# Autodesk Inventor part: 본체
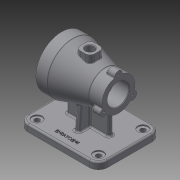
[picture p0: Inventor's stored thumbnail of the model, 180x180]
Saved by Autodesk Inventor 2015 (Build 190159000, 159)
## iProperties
Created: 2021-10
Part Number: 본체
Material: 일반
Document SubType Name: Modeling
Designer: 1019876
Density: 1 g/cm^3
Appearance: 기본값
Author: 1019876
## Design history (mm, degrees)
sketch "스케치1"
  geometry: L1 (70, 55)-(-70, 55); L2 (-70, 55)-(-70, -55); L3 (-70, -55)-(70, -55); L4 (70, -55)-(70, 55); L5 (70, 55)-(-70, -55); L6 (-70, 55)-(70, -55); 1 further point
  constraints: 12 end point, 2 midpoint, 2 parallel, 1 horizontal, 1 perpendicular
  dimensions: "d0" = 140 distance of L3.end L2.end; "d1" = 110 distance of L2.end L1.end
extrude "돌출1" new body sketch "스케치1" distance "d2" = 12; taper "d3" = 0 deg
sketch "스케치2"
  geometry: L1 (-54, -39)-(54, -39); L2 (54, -39)-(54, 39); L3 (54, 39)-(-54, 39); L4 (-54, 39)-(-54, -39); L5 (-54, -39)-(54, 39); L6 (54, -39)-(-54, 39); 5 further points
  constraints: 12 end point, 4 coincident, 2 midpoint, 2 parallel, 1 horizontal, 1 perpendicular
  dimensions: "d4" = 108 distance of L3.end L2.end; "d5" = 78 distance of L2.end L1.end
hole "구멍1" sketch "스케치2" at (-54, 39), (54, -39), (54, 39), (-54, -39) diameter "d6" = 9; stored, may be unused: countersink angle "d10" = 90 deg, drill point angle "d12" = 118 deg; dims "d7" = 6, "d8" = 18, "d9" = 2, "d11" = 28
sketch "스케치3"
  geometry: L1 (-50, 82)-(50, 82); L2 (-50, 82)-(-50, 127); L3 (-50, 127)-(-30, 127); L4 (-30, 127)-(27, 111); L5 (27, 111)-(50, 111); L6 (50, 111)-(50, 82); L7 (70, 0)-(-70, 0) reference; 2 further points
  constraints: 12 end point, 1 horizontal, 1 midpoint, 1 parallel, 1 perpendicular, 1 vertical, 1 vertical alignment
  dimensions: "d13" = 90 diameter of L3 L1; "d15" = 82 distance between parallel lines of L7 L1; "d16" = 20 distance of L2.end L3.end; "d18" = 23 distance from line of L6 L4.end; "d19" = 100 distance between parallel lines of L6 L2; "d21" = 58 diameter of L5 L1
revolve "회전1" sketch "스케치3" stored, may be unused: angle "d22" = 90 deg
sketch "스케치4"
  geometry: L1 (0, 29)-(0, 0); L2 (0, 0)-(-25.115, -14.5); L3 (0, 0)-(25.115, -14.5); C1 r 7 at (0, 29); C2 r 7 at (-25.115, -14.5); C3 r 7 at (25.115, -14.5); A1 r 29 centre (0, 0) between (0, 29) and (-25.115, -14.5) reference; 1 further point
  constraints: 6 end point, 3 centre point, 3 point on circle, 2 coincident, 1 vertical, 1 vertical alignment
  dimensions: "d23" = 14 diameter of C1; "d24" = 120 deg angle of L2 L1; "d25" = 120 deg angle of L2 L3; "d26" = 14 diameter of C2; "d27" = 14 diameter of C3
extrude "돌출2" join sketch "스케치4" distance "d28" = 15; taper "d29" = 0 deg
node "작업 평면1"
sketch "스케치5"
  geometry: L1 (12.5, 12.5)-(-12.5, 12.5); L2 (-12.5, 12.5)-(-12.5, -12.5); L3 (-12.5, -12.5)-(12.5, -12.5); L4 (12.5, -12.5)-(12.5, 12.5); L5 (12.5, 12.5)-(-12.5, -12.5); L6 (-12.5, 12.5)-(12.5, -12.5); 1 further point
  constraints: 12 end point, 2 midpoint, 2 parallel, 1 horizontal, 1 perpendicular
  dimensions: "d31" = 25 distance of L3.end L2.end; "d32" = 25 distance of L2.end L1.end
extrude "돌출3" join sketch "스케치5" distance "d33" = 23.5; taper "d34" = 0 deg
sketch "스케치6"
  geometry: 2 further points
  constraints: 1 coincident
hole "구멍2" sketch "스케치6" at (0, 0) diameter "d35" = 15; stored, may be unused: countersink angle "d39" = 90 deg, drill point angle "d41" = 118 deg; dims "d36" = 6, "d37" = 18, "d38" = 2, "d40" = 38.25
sketch "스케치7"
  geometry: L1 (-50, 37)-(-50, 127) reference; L2 (-50, 82)-(50, 82); L3 (50, 73.94)-(50, 110.155) reference; L4 (-50, 82)-(-50, 113); L5 (-50, 113)-(-30, 113); L6 (-27, 110)-(-27, 110); L7 (-24, 107)-(17, 107); L8 (20, 104)-(20, 104); L9 (23, 101)-(50, 101); L10 (50, 82)-(50, 101); A1 r 3 centre (-30, 110) between (-27, 110) and (-30, 113); A2 r 3 centre (-24, 110) between (-27, 110) and (-24, 107); A3 r 3 centre (17, 104) between (20, 104) and (17, 107); A4 r 3 centre (23, 104) between (20, 104) and (23, 101); 3 further points
  constraints: 16 end point, 8 point on circle, 8 tangent, 7 point on line, 5 perpendicular, 4 centre point, 3 equal radius, 2 horizontal, 1 midpoint
  dimensions: "d42" = 23 distance between parallel lines of L6 L1; "d43" = 47 distance of point (-27, 107) point (20, 107); "d44" = 62 diameter of L5 L2; "d45" = 50 diameter of L7 L2; "d46" = 38 diameter of L9 L2; "d47" = 3 radius of A1
revolve "회전2" sketch "스케치7" stored, may be unused: angle "d48" = 90 deg
sketch "스케치8"
  geometry: L1 (-37, -4)-(37, -4); L2 (37, -4)-(37, 4); L3 (37, 4)-(-37, 4); L4 (-37, 4)-(-37, -4); L5 (-37, -4)-(37, 4); L6 (37, -4)-(-37, 4); L7 (-4, -24)-(4, -24); L8 (4, -24)-(4, 24); L9 (4, 24)-(-4, 24); L10 (-4, 24)-(-4, -24); L11 (-4, -24)-(4, 24); L12 (4, -24)-(-4, 24); 1 further point
  constraints: 24 end point, 4 midpoint, 4 parallel, 2 horizontal, 2 perpendicular
  dimensions: "d49" = 74 distance of L3.end L2.end; "d50" = 8 distance of L2.end L1.end; "d51" = 8 distance of L9.end L8.end; "d52" = 48 distance of L8.end L7.end
extrude "돌출4" join sketch "스케치8" stored distance "d53" = 23.5; taper "d54" = 0 deg
feature "면 기울기1" dims angle "d55" = 5 deg
feature "면 기울기2" dims angle "d56" = 5 deg
sketch "스케치9" dims "d57" = 80
  geometry: C1 r 31 at (0, 0) reference; C2 r 45 at (0, 0) reference; 8 further points
  constraints: 2 vertical alignment, 1 coincident, 9 other
  dimensions: "d60" = 360 deg dimension on point (0, 0) point (0, 40) (derived)
hole "구멍3" sketch "스케치9" at (0, 40), (-34.641, 20), (-34.641, -20), (0, -40), (34.641, -20), (34.641, 20) diameter "d62" = 3.242; stored, may be unused: countersink angle "d66" = 90 deg, drill point angle "d68" = 118 deg; dims "d63" = 9, "d64" = 18, "d65" = 2, "d67" = 11
sketch "스케치10"
  geometry: A1 r 7 centre (0, 0) between (6.949, -0.845) and (-6.949, -0.845) reference; A2 r 7 centre (-25.115, -43.5) between (-27.858, -37.06) and (-20.909, -49.095) reference; A3 r 7 centre (25.115, -43.5) between (20.909, -49.095) and (27.858, -37.06) reference; 4 further points
  constraints: 3 coincident
hole "구멍4" sketch "스케치10" at (0, 0), (-25.115, -43.5), (25.115, -43.5) diameter "d69" = 3.242; stored, may be unused: countersink angle "d73" = 90 deg, drill point angle "d75" = 118 deg; dims "d70" = 9, "d71" = 18, "d72" = 2, "d74" = 11
fillet "모깎기1" dims "d76" = 16
fillet "모깎기2" dims "d77" = 8
fillet "모깎기3" dims "d78" = 3
fillet "모깎기4" dims "d79" = 1
fillet "모깎기5" dims "d80" = 3
fillet "모깎기6" dims "d81" = 3
chamfer "모따기1" distance "d82" = 1; stored, may be unused: second distance "d83" = 2, angle "d84" = 45 deg
node "작업 평면2"
sketch "스케치11"
  geometry: L1 (-54, -55)-(54, -55) reference; 2 further points
  constraints: 1 vertical alignment, 1 other
  dimensions: "d86" = 15 distance from line of L1 point (0, -40)
feature "엠보싱1" sketch "스케치11" dims "d0" = 140, "d1" = 110, "d13" = 90, "d15" = 82, "d16" = 20, "d18" = 23, "d19" = 100, "d21" = 58, "d87" = 0.5, "d88" = 0
chamfer "모따기2" distance "d89" = 1; stored, may be unused: second distance "d90" = 2, angle "d91" = 45 deg
node "솔리드1"
other parameters: "d30" = 127
